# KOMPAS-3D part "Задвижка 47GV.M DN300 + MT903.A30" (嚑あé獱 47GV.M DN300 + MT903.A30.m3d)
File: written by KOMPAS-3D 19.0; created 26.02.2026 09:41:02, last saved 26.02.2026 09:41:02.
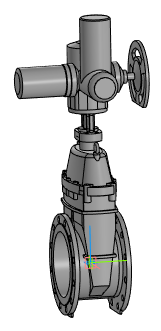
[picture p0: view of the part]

Document properties: Автор: Энергия; Полное имя файла: 47GV.M DN300\Задвижка 47GV.M DN300 с маховиком.a3d

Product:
- Part/product: Задвижка 47GV.M DN300 + MT903.A30
    Масса: 397.224
  - Component: Задвижка с обрезиненным клином DN300. Сборочный чертеж  | designation DR.47GVM.300.16.00.000СБ  | pos. 0  | Масса: 108.933; Раздел спецификации: Документация; Форматы листов документа: 2xA3; source file: ..\..\47GVM\DR.47GVM.300.16.00.000\DR.47GVM.300.16.00.000 СБ - Задвижка с обрезиненным клином DN300.cdw

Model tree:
1. Операция без истории:1

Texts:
  Точка начала. Х
  Точка начала. Y
  Точка начала. Z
